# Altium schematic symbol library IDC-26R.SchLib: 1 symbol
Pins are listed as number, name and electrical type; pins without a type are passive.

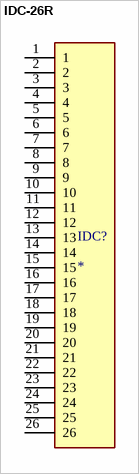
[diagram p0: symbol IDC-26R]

## IDC-26R
designator IDC?
MP: 1-103167-0
footprint IDC-26R
pins: 1, 2, 3, 4, 5, 6, 7, 8, 9, 10, 11, 12, 13, 14, 15, 16, 17, 18, 19, 20, 21, 22, 23, 24, 25, 26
